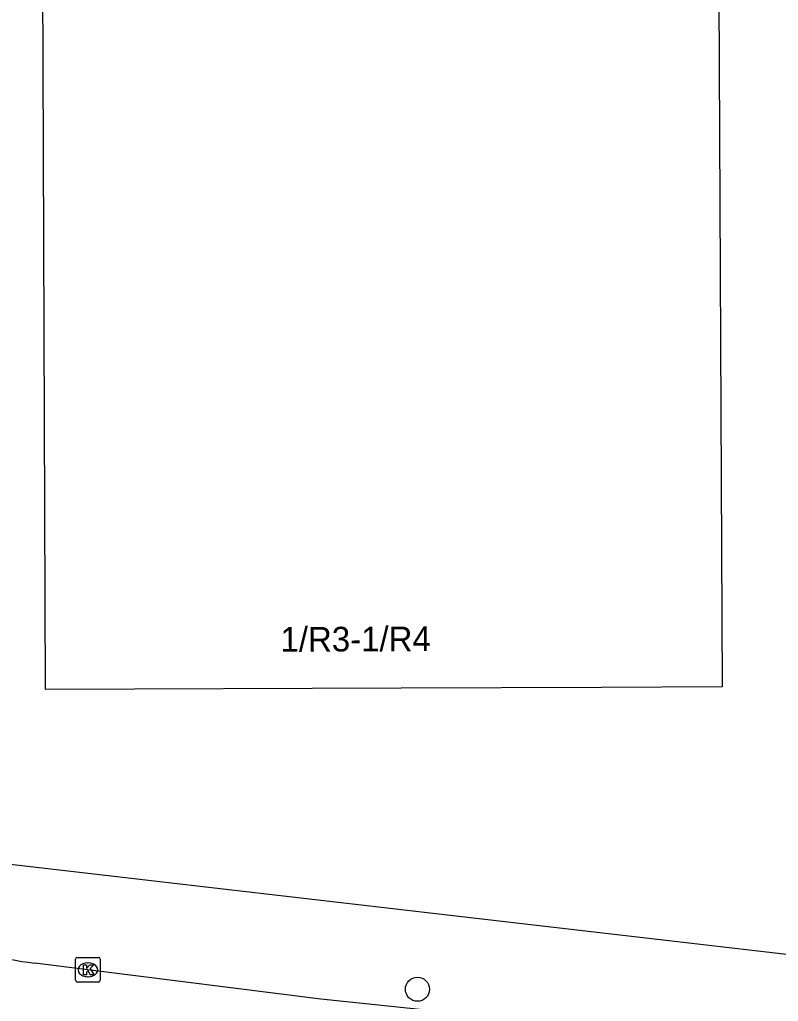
# Model space of a CAD drawing. Extents: x 161243 to 161752, y 384138 to 384885.
# Drawn here: x 161334.45 to 161365.22, y 384665.48 to 384705.31 of the extents above; entities that cross this region are included whole.
import ezdxf

# ---------------------------------------------------------------- set-up
doc = ezdxf.new("R2010")
doc.units = 0
for name, color, linetype in [('IMGEO_Boom', 7, 'Continuous'), ('IMGEO_Kolk', 7, 'Continuous'), ('IMGEO_Pand', 7, 'Continuous'), ('IMGEO_Pand_nummerreeks', 7, 'Continuous'), ('IMGEO_Rijbaan_lokaal_gesloten', 7, 'Continuous'), ('IMGEO_Voetpad_open', 7, 'Continuous')]:
    doc.layers.add(name, color=color, linetype=linetype)

msp = doc.modelspace()

# ---------------------------------------------------------------- linework, layer by layer
at = {"layer": 'IMGEO_Boom'}
msp.add_circle((161350.585, 384665.971), 0.489, dxfattribs=at)
at = {"layer": 'IMGEO_Kolk'}
for p, q in [((161336.719, 384666.336), (161336.719, 384667.188)), ((161336.794, 384667.262), (161337.646, 384667.262)), ((161337.72, 384667.188), (161337.72, 384666.336)), ((161337.207, 384667.042), (161337.232, 384667.042)), ((161337.23, 384666.482), (161337.205, 384666.482)), ((161337.646, 384666.262), (161336.794, 384666.262))]:
    msp.add_line(p, q, dxfattribs=at)
for points in [[(161336.719, 384666.336), (161336.719, 384667.188)], [(161336.794, 384667.262), (161337.646, 384667.262)], [(161337.72, 384667.188), (161337.72, 384666.336)], [(161337.04, 384666.962), (161337.163, 384666.962), (161337.163, 384666.811), (161337.293, 384666.962), (161337.457, 384666.962), (161337.311, 384666.811), (161337.464, 384666.562), (161337.312, 384666.562), (161337.227, 384666.726), (161337.163, 384666.659), (161337.163, 384666.562), (161337.04, 384666.562), (161337.04, 384666.962)], [(161337.646, 384666.262), (161336.794, 384666.262)]]:
    msp.add_lwpolyline(points, dxfattribs=at)
for centre, start, end in [((161336.796, 384667.186), 91.552, 178.448), ((161336.796, 384667.186), 91.552, 178.448), ((161337.644, 384667.186), 1.552, 88.448), ((161337.644, 384667.186), 1.552, 88.448), ((161336.796, 384666.338), 181.552, 268.448), ((161336.796, 384666.338), 181.552, 268.448), ((161337.644, 384666.338), 271.552, 358.448), ((161337.644, 384666.338), 271.552, 358.448)]:
    msp.add_arc(centre, 0.0765, start, end, dxfattribs=at)
for centre, major_axis, ratio, start_param, end_param in [((161337.206, 384666.762), (-0.387, 0.002), 0.722429, 4.712389, 7.853982), ((161337.231, 384666.762), (-0.39, 0.002), 0.717154, 1.570796, 4.712389)]:
    msp.add_ellipse(centre, major_axis=major_axis, ratio=ratio, start_param=start_param, end_param=end_param, dxfattribs=at)
at = {"layer": 'IMGEO_Pand'}
msp.add_lwpolyline([(161362.789, 384709.056), (161362.941, 384678.236), (161358.051, 384678.216), (161349.923, 384678.184), (161335.494, 384678.126), (161335.415, 384699.945), (161335.39, 384706.897)], dxfattribs=at)
at = {"layer": 'IMGEO_Rijbaan_lokaal_gesloten'}
msp.add_lwpolyline([(161385.812, 384661.078), (161378.041, 384661.982), (161371.462, 384662.748), (161352.098, 384665), (161346.668, 384665.574), (161337.22, 384666.762), (161335.063, 384667.031)], dxfattribs=at)
msp.add_arc((161336.615, 384680.246), 13.306, 245.121, 263.3027, dxfattribs=at)
at = {"layer": 'IMGEO_Voetpad_open'}
msp.add_lwpolyline([(161370.695, 384666.781), (161333.364, 384671.12), (161322.964, 384672.434), (161316.855, 384673.118)], dxfattribs=at)

# ---------------------------------------------------------------- texts
at = {"layer": 'IMGEO_Pand_nummerreeks'}
msp.add_text('1/R3-1/R4', height=1, rotation=0.2235, dxfattribs=at).set_placement((161345.033, 384679.665))

doc.saveas('drawing.dxf')
